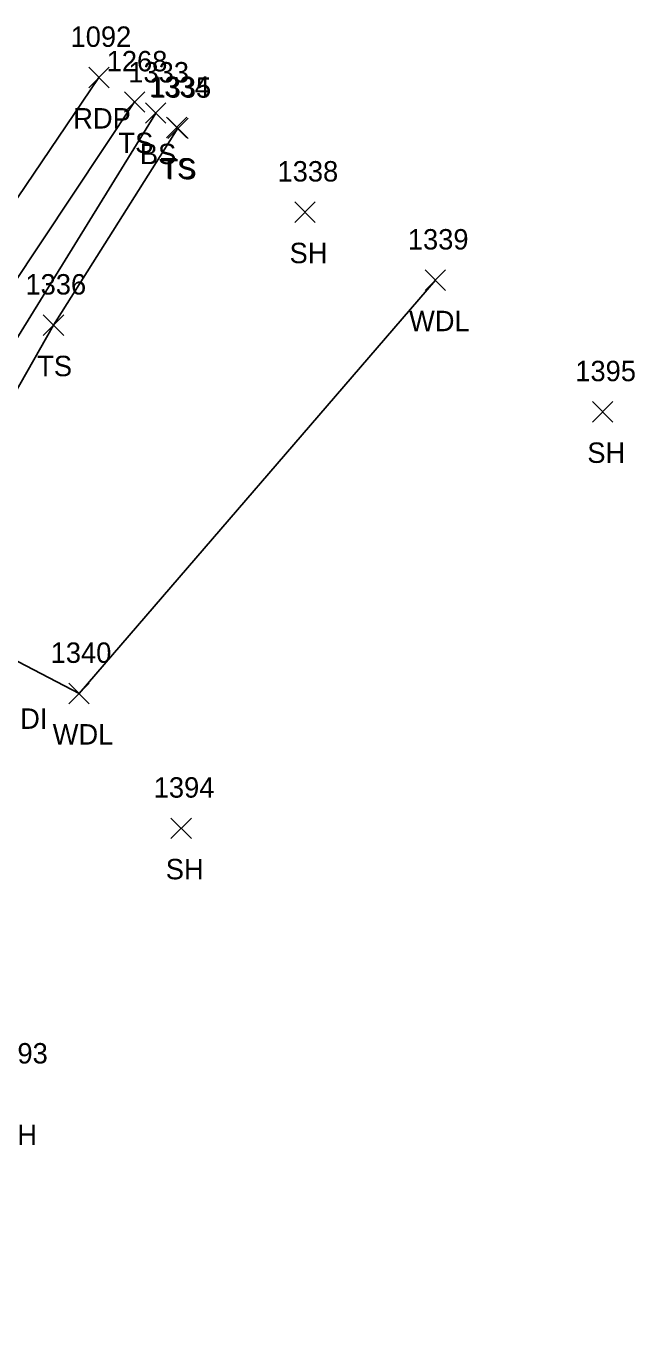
# Model space of a CAD drawing. Extents: x 1634209 to 1639641, y 608564 to 612258.
# Drawn here: x 1639581.2 to 1639640.8, y 612059.5 to 612187.5 of the extents above; entities that cross this region are included whole.
import ezdxf

# ---------------------------------------------------------------- set-up
doc = ezdxf.new("R2010")
doc.units = 0
for name, color, linetype in [('D_C', 7, 'Continuous'), ('L_A', 7, 'Continuous'), ('L_I', 7, 'Continuous'), ('L_TIC', 7, 'Continuous'), ('LAWA', 7, 'Continuous'), ('LELB', 7, 'Continuous'), ('P_A', 7, 'Continuous'), ('P_I', 7, 'Continuous'), ('P_TIC', 7, 'Continuous'), ('PET', 7, 'Continuous')]:
    doc.layers.add(name, color=color, linetype=linetype)

msp = doc.modelspace()

# ---------------------------------------------------------------- linework, layer by layer
at = {"layer": 'L_TIC'}
for points in [[(1639590.82, 612179.12), (1639592.82, 612181.12)], [(1639592.82, 612179.12), (1639590.82, 612181.12)], [(1639592.89, 612178.03), (1639594.89, 612180.03)], [(1639594.89, 612178.03), (1639592.89, 612180.03)], [(1639594.94, 612176.62), (1639596.94, 612178.62)], [(1639596.94, 612176.62), (1639594.94, 612178.62)], [(1639595.06, 612176.54), (1639597.06, 612178.54)], [(1639597.06, 612176.54), (1639595.06, 612178.54)], [(1639607.51, 612168.33), (1639609.51, 612170.33)], [(1639609.51, 612168.33), (1639607.51, 612170.33)], [(1639620.29, 612161.67), (1639622.29, 612163.67)], [(1639622.29, 612161.67), (1639620.29, 612163.67)], [(1639582.87, 612157.26), (1639584.87, 612159.26)], [(1639584.87, 612157.26), (1639582.87, 612159.26)], [(1639636.69, 612148.77), (1639638.69, 612150.77)], [(1639638.69, 612148.77), (1639636.69, 612150.77)], [(1639585.37, 612121.18), (1639587.37, 612123.18)], [(1639587.37, 612121.18), (1639585.37, 612123.18)], [(1639595.38, 612107.98), (1639597.38, 612109.98)], [(1639597.38, 612107.98), (1639595.38, 612109.98)]]:
    msp.add_lwpolyline(points, dxfattribs=at)
at = {"layer": 'LAWA'}
msp.add_lwpolyline([(1639621.29, 612162.67), (1639586.37, 612122.18), (1639574.47, 612128.38), (1639569.45, 612130.12), (1639568.95, 612119.64), (1639554.1, 612098.18), (1639539.81, 612087.62), (1639526.58, 612068.13), (1639518.72, 612053.78), (1639510.6, 612040.7), (1639492.01, 612011.11), (1639478.47, 611981.43), (1639467.99, 611958.08), (1639459.16, 611932.72), (1639452.06, 611918.05), (1639447.34, 611897.74), (1639441.05, 611876.68), (1639428.25, 611845.92)], dxfattribs=at)
at = {"layer": 'LELB'}
for points in [[(1639591.82, 612180.12), (1639567.53, 612143.68), (1639557.91, 612130.49)], [(1639564.44, 612132.28), (1639576.09, 612150.22), (1639593.89, 612179.03)], [(1639595.94, 612177.62), (1639596.06, 612177.54), (1639583.87, 612158.26), (1639569.4, 612132.83)]]:
    msp.add_lwpolyline(points, dxfattribs=at)
at = {"layer": 'P_TIC'}
for points in [[(1639587.32, 612181.52), (1639589.32, 612183.52)], [(1639589.32, 612181.52), (1639587.32, 612183.52)]]:
    msp.add_lwpolyline(points, dxfattribs=at)
at = {"layer": 'PET'}
msp.add_lwpolyline([(1639245.26, 611428.04), (1639265.27, 611462.65), (1639285.72, 611496.98), (1639297.96, 611518.63), (1639312.46, 611545.86), (1639331.24, 611585.47), (1639351.91, 611632.95), (1639369.29, 611681.55), (1639385.15, 611732.94), (1639399.72, 611782.78), (1639415.55, 611836.4), (1639431.27, 611887.12), (1639449.51, 611937.71), (1639468.81, 611983.24), (1639484.71, 612016.46), (1639503.95, 612051.42), (1639527.63, 612090.72), (1639556.4, 612135.38), (1639588.32, 612182.52)], dxfattribs=at)

# ---------------------------------------------------------------- texts
at = {"layer": 'D_C'}
msp.add_text('NEW GRATE ON OLD ONE THROAT DI', height=2, dxfattribs=at).set_placement((1639534.39, 612118.72))
at = {"layer": 'L_A'}
for s, p in [('TS', (1639590.23, 612175.12)), ('BS', (1639592.33, 612174.03)), ('TS', (1639594.35, 612172.62)), ('TS', (1639594.47, 612172.54)), ('SH', (1639607, 612164.33)), ('WDL', (1639618.71, 612157.67)), ('TS', (1639582.27, 612153.26)), ('SH', (1639636.18, 612144.77)), ('WDL', (1639583.79, 612117.18)), ('SH', (1639594.87, 612103.98)), ('SH', (1639578.54, 612077.94))]:
    msp.add_text(s, height=2, dxfattribs=at).set_placement(p)
at = {"layer": 'L_I'}
for s, p in [('1268', (1639589.08, 612183.12)), ('1333', (1639591.2, 612182.03)), ('1334', (1639593.24, 612180.62)), ('1335', (1639593.37, 612180.54)), ('1338', (1639605.82, 612172.33)), ('1339', (1639618.59, 612165.67)), ('1336', (1639581.12, 612161.26)), ('1395', (1639635, 612152.77)), ('1340', (1639583.59, 612125.18)), ('1394', (1639593.69, 612111.98)), ('1393', (1639577.36, 612085.94))]:
    msp.add_text(s, height=2, dxfattribs=at).set_placement(p)
at = {"layer": 'P_A'}
msp.add_text('RDP', height=2, dxfattribs=at).set_placement((1639585.8, 612177.52))
at = {"layer": 'P_I'}
msp.add_text('1092', height=2, dxfattribs=at).set_placement((1639585.54, 612185.52))

doc.saveas('drawing.dxf')
